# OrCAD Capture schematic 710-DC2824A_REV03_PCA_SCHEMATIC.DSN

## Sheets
1 PAGE3: size A
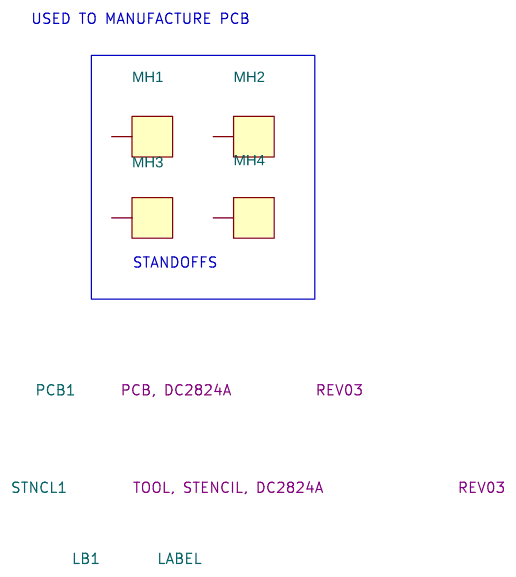
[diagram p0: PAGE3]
2 PAGE2: size Custom; company: ANALOG DEVICES; note: DEMO BOARD BILL OF MATERIALS; note: 25A MONOLITHIC SYNCHRONOUS STEP-DOWN
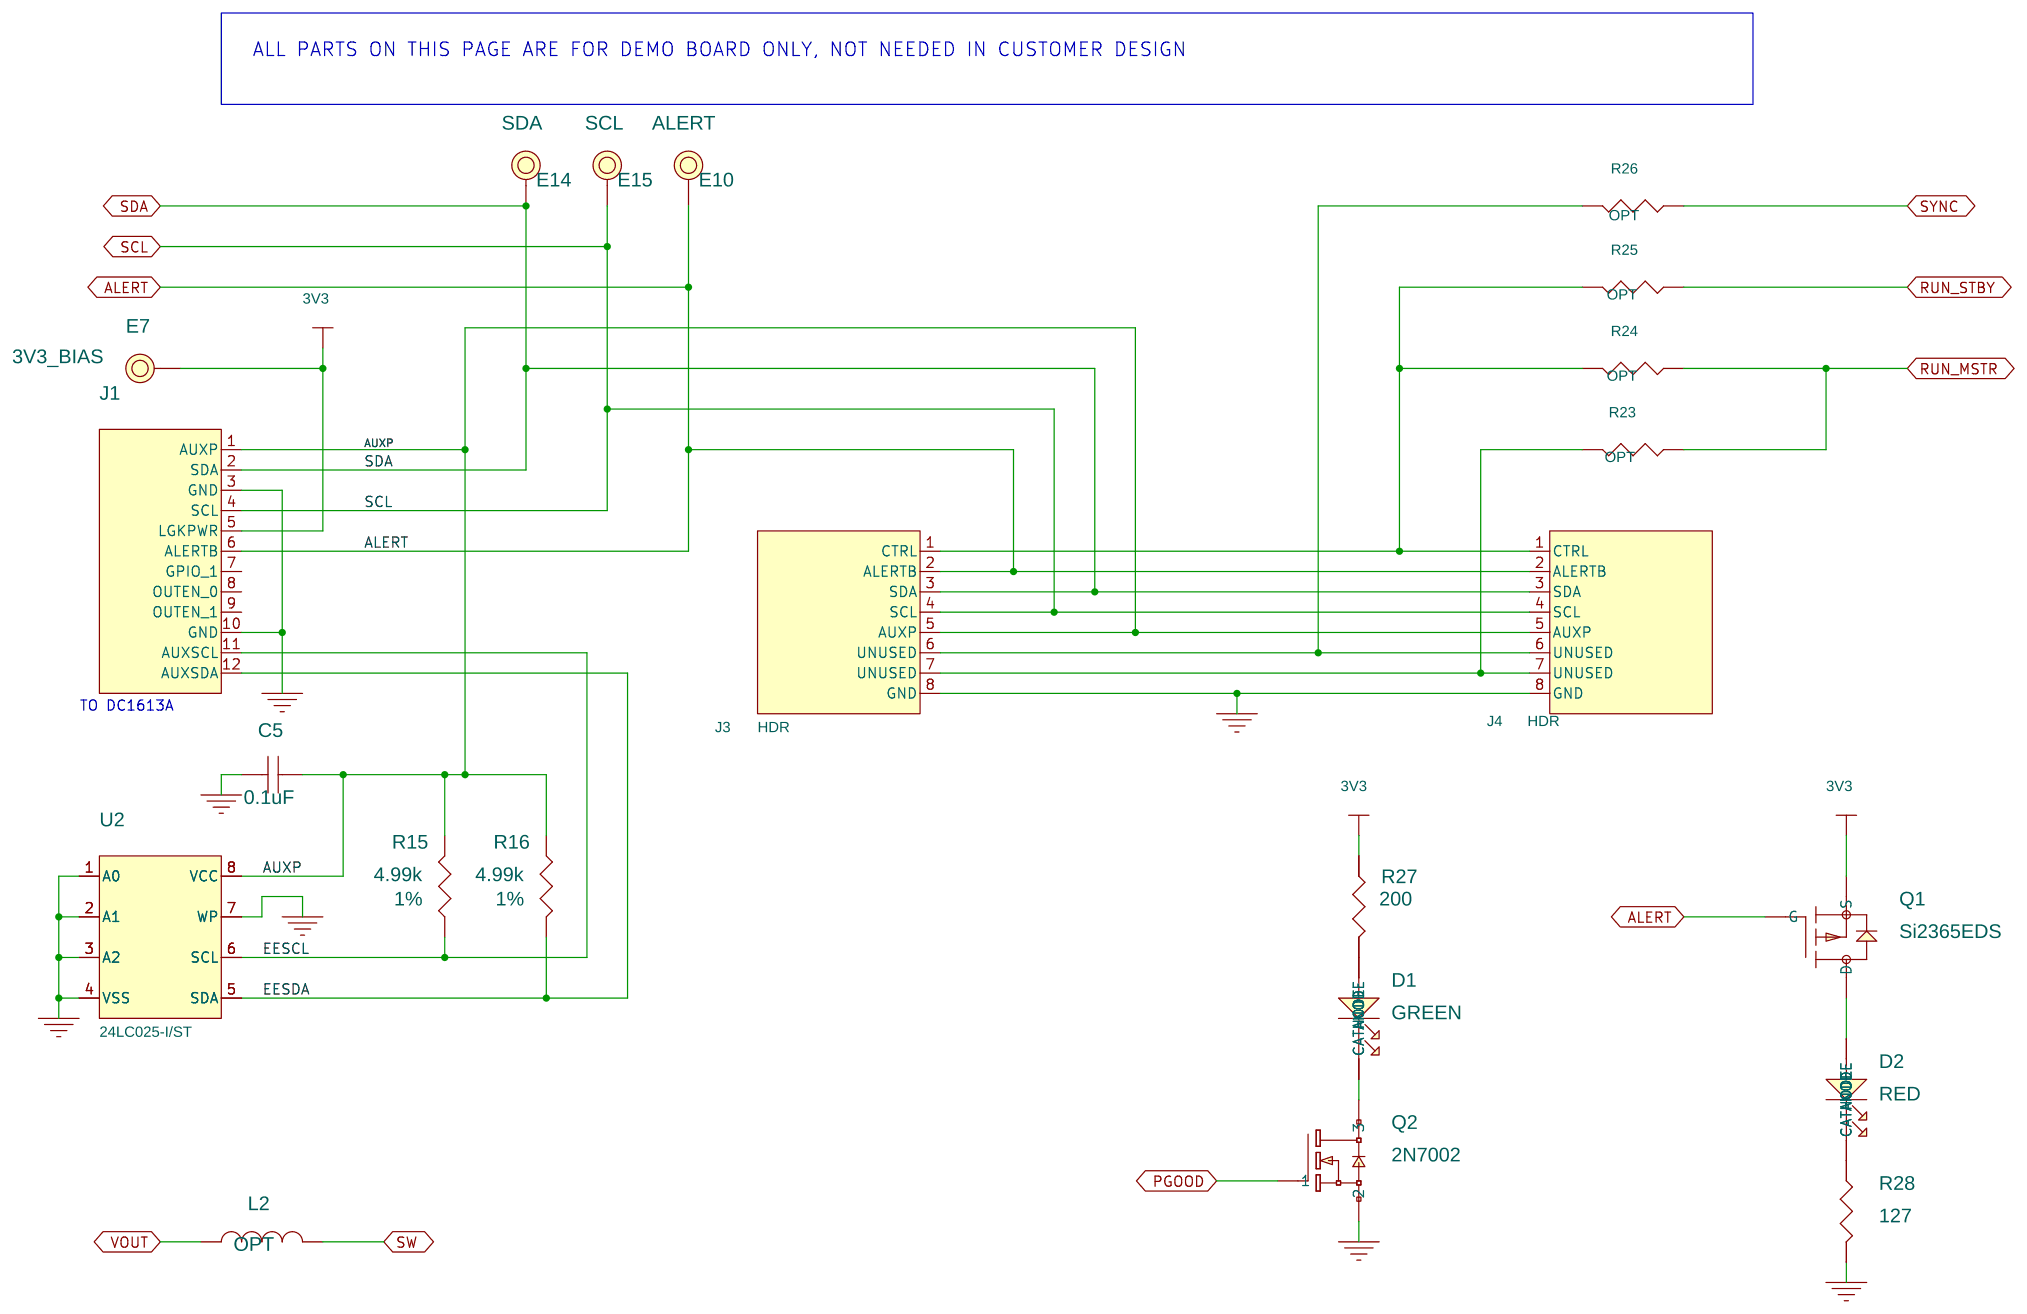
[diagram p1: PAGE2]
3 PAGE1: size Custom; company: ANALOG DEVICES; note: DEMO BOARD BILL OF MATERIALS; note: 25A MONOLITHIC SYNCHRONOUS STEP-DOWN
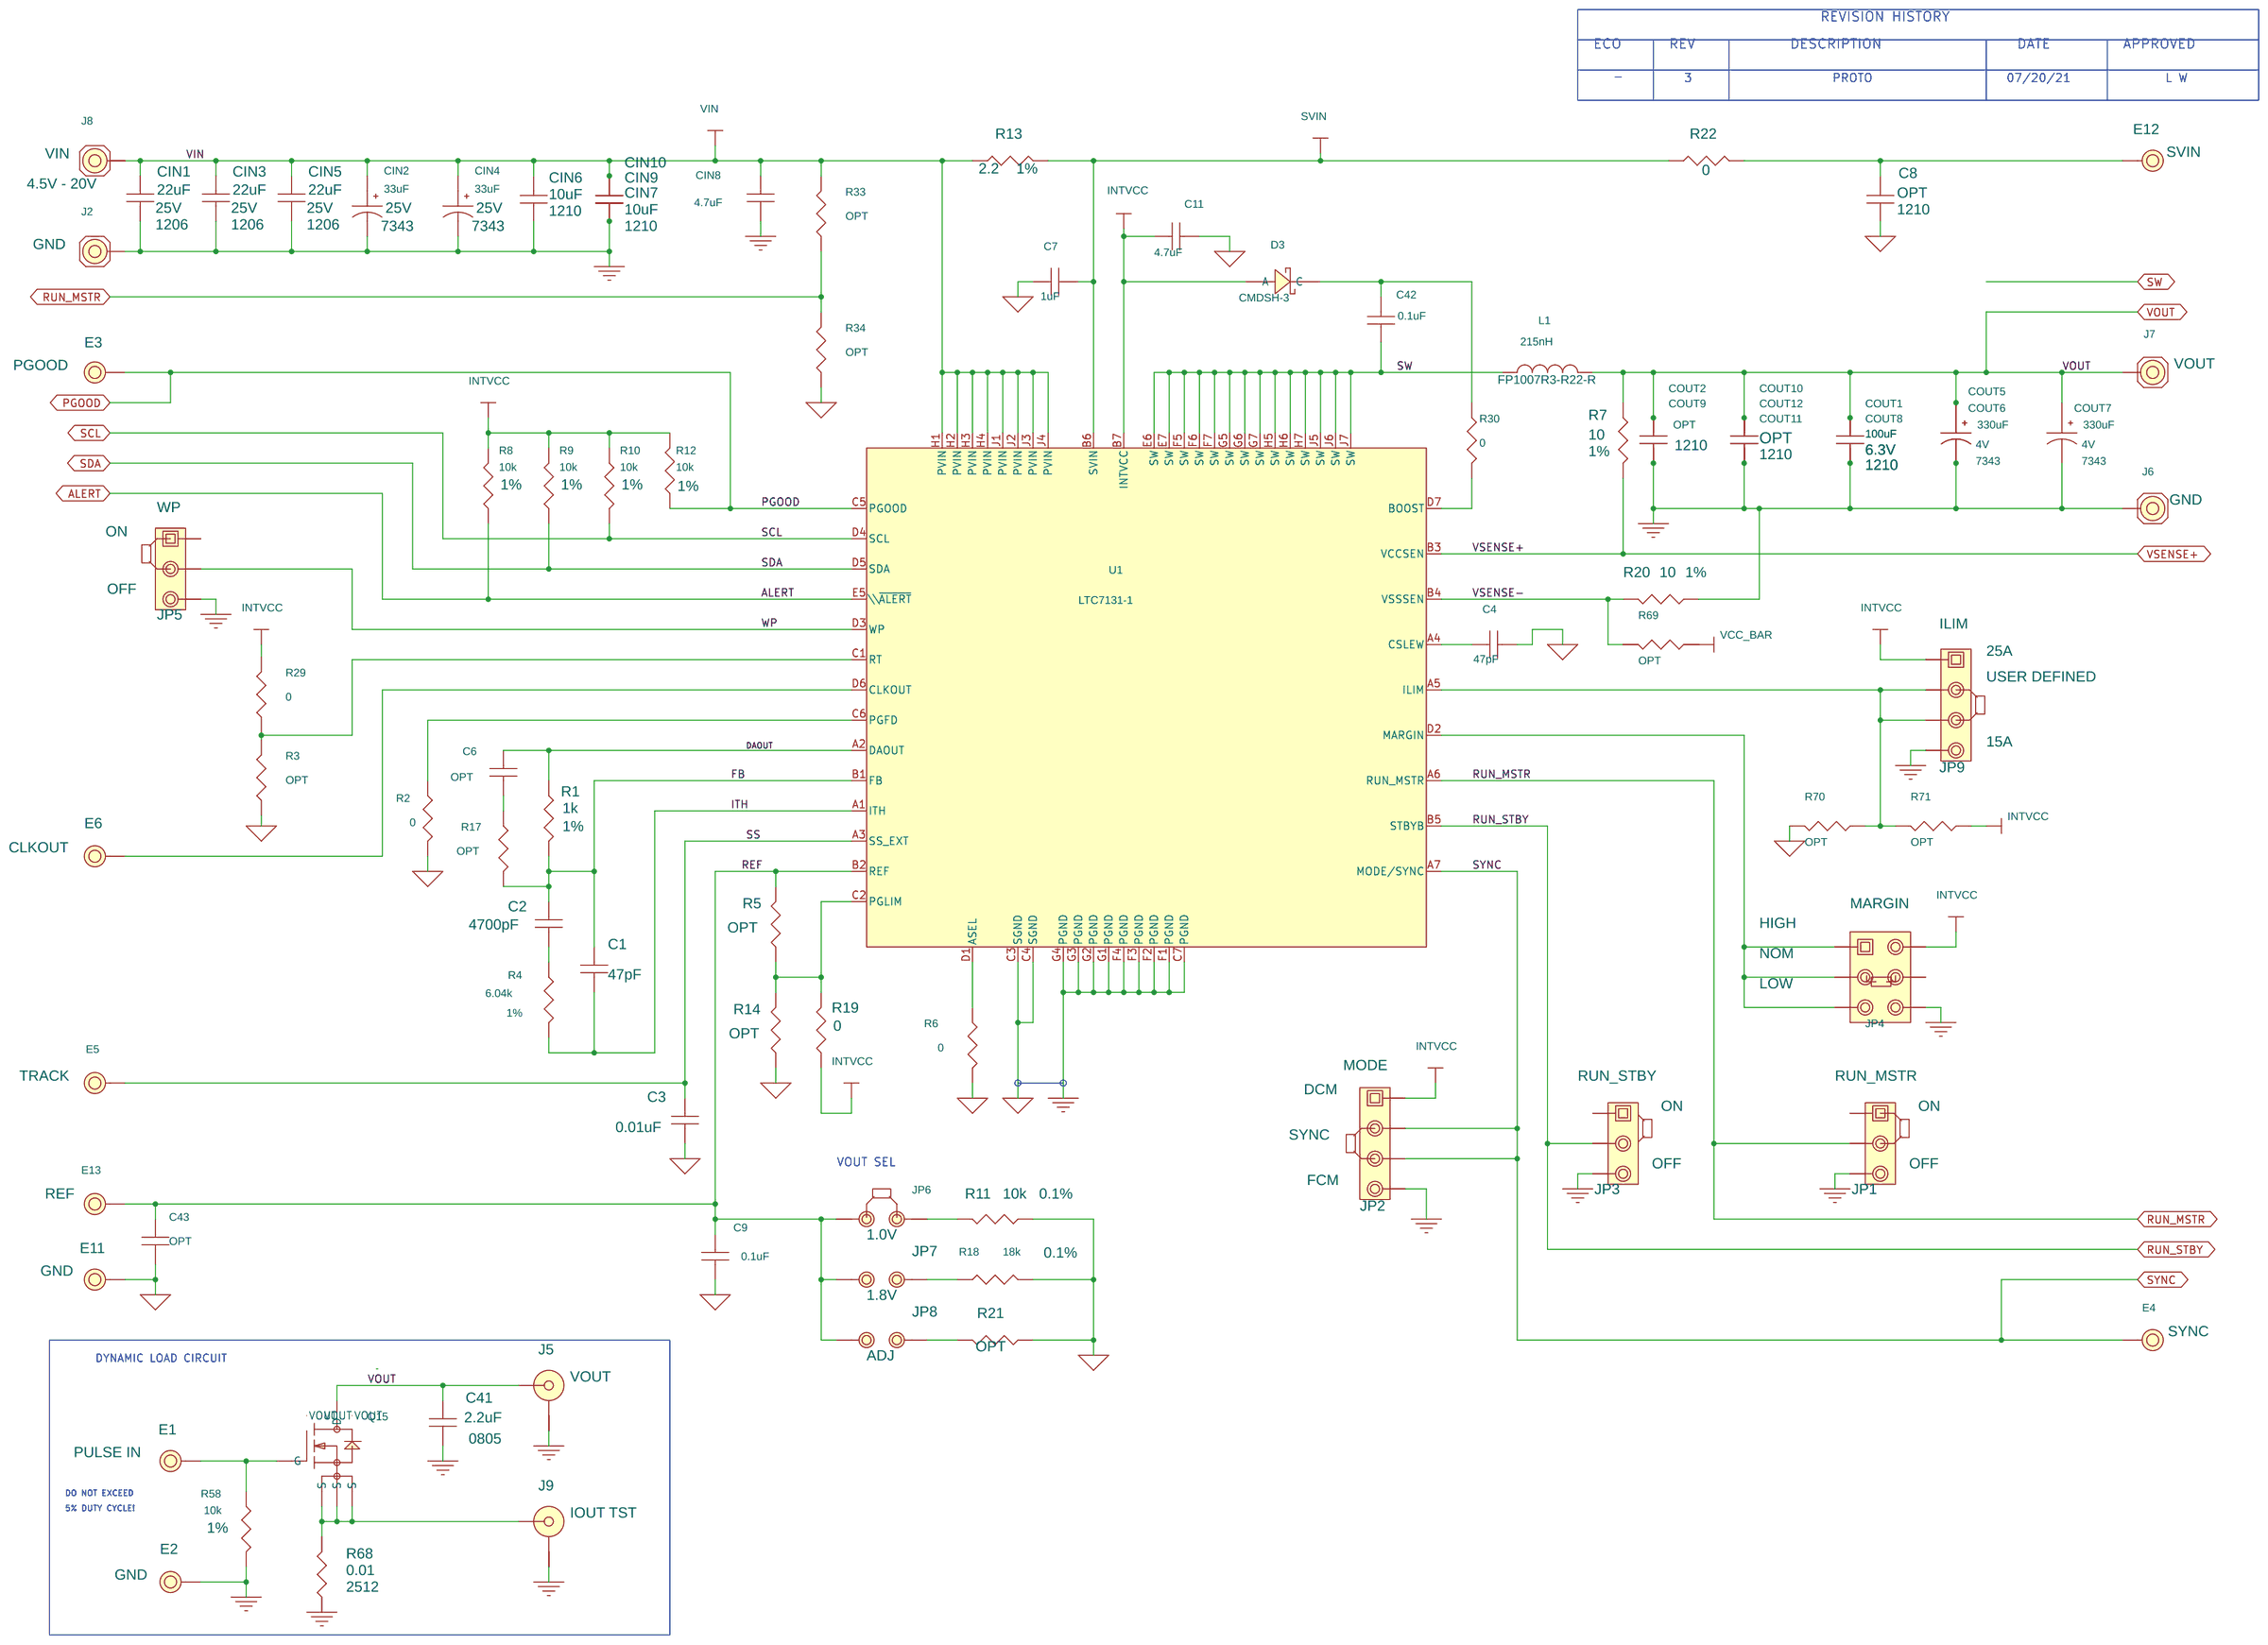
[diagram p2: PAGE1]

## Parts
sheet PAGE1
C1  47pF  [CC0603N]
C2  4700pF  [CC0603N]
C3  0.01uF  [CC0603N]
C4  47pF  [CC0603N]
C6  OPT  [CC0603N]
C7  1uF  [CC0603N]
C8  OPT  [CC1210N]
C9  0.1uF  [CC0603N]
C11  4.7uF  [CC0603N]
C41  2.2uF  [CC0805N]
C42  0.1uF  [CC0603N]
C43  OPT  [CC0603N]
CIN1  22uF  [CC1206N]
CIN2  33uF  [CAPMP7343N]
CIN3  22uF  [CC1206N]
CIN4  33uF  [CAPMP7343N]
CIN5  22uF  [CC1206N]
CIN6  10uF  [CC1210N]
CIN7  10uF  [CC1210N]
CIN8  4.7uF  [CC0603N]
CIN9  10uF  [CC1210N]
CIN10  10uF  [CC1210N]
COUT1  100uF  [CC1210N]
COUT2  OPT  [CC1210N]
COUT5  330uF  [CAPMP7343N]
COUT6  330uF  [CAPMP7343N]
COUT7  330uF  [CAPMP7343N]
COUT8  100uF  [CC1210N]
COUT9  OPT  [CC1210N]
COUT10  OPT  [CC1210N]
COUT11  OPT  [CC1210N]
COUT12  OPT  [CC1210N]
D3  CMDSH-3  [SOD-323M]
E1  TEST POINT  [MILLMAX2501]
E2  TEST POINT  [MILLMAX2501]
E3  TEST POINT  [MILLMAX2501]
E4  TEST POINT  [MILLMAX2501]
E5  TEST POINT  [MILLMAX2501]
E6  TEST POINT  [MILLMAX2501]
E11  TEST POINT  [MILLMAX2501]
E12  TEST POINT  [MILLMAX2501]
E13  TEST POINT  [MILLMAX2501]
J2  STUD,#10-32  [PENN-KFH-032]
J5  RF,BNC  [CONNEX-112404]
J6  STUD,#10-32  [PENN-KFH-032]
J7  STUD,#10-32  [PENN-KFH-032]
J8  STUD,#10-32  [PENN-KFH-032]
J9  RF,BNC  [CONNEX-112404]
JP1  HDR  [HD1X3-079]
JP2  HDR  [HD1X4-079]
JP3  HDR  [HD1X3-079]
JP4  HDR.  [HD2X3-079]
JP5  HDR  [HD1X3-079]
JP6  HDR  [SIP\2P\2MM]
JP7  HDR  [SIP\2P\2MM]
JP8  HDR  [SIP\2P\2MM]
JP9  HDR  [HD1X4-079]
L1  215nH  [EATON-FP1007]
Q15  RJK0305DPB-02  [RENESAS-LFPAK]
R1  1k  [CR0603N]
R2  0  [CR0603N]
R3  OPT  [CR0603N]
R4  6.04k  [CR0603N]
R5  OPT  [CR0603N]
R6  0  [CR0603N]
R7  10  [CR0603N]
R8  10k  [CR0603N]
R9  10k  [CR0603N]
R10  10k  [CR0603N]
R11  10k  [CR0603N]
R12  10k  [CR0603N]
R13  2.2  [CR0603N]
R14  OPT  [CR0603N]
R17  OPT  [CR0603N]
R18  18k  [CR0603N]
R19  0  [CR0603N]
R20  10  [CR0603N]
R21  OPT  [CR0603N]
R22  0  [CR0603N]
R29  0  [CR0603N]
R30  0  [CR0603N]
R33  OPT  [CR0603N]
R34  OPT  [CR0603N]
R58  10k  [CR0603N]
R68  0.01  [CR2512N]
R69  OPT  [CR0603N]
R70  OPT  [CR0603N]
R71  OPT  [CR0603N]
U1  LTC7131-1  [LTC-BGA-63-1988]
XJP1  SHUNT
XJP2  SHUNT
XJP3  SHUNT
XJP4  SHUNT
XJP5  SHUNT
XJP6  SHUNT
XJP9  SHUNT
sheet PAGE2
C5  0.1uF  [CC0603N]
D1  GREEN  [LED_0603]
D2  RED  [LED_0603]
E7  TEST POINT  [MILLMAX2501]
E10  TEST POINT  [MILLMAX2501]
E14  TEST POINT  [MILLMAX2501]
E15  TEST POINT  [MILLMAX2501]
J1  SHROUDED HDR  [HD2X6-079-MOLEX]
J3  HDR  [NPPN042FJFN]
J4  HDR  [NPPN042FJFN-RC]
L2  OPT  [IND\CLCRFT\XEL6030]
Q1  Si2365EDS  [SOT23-3N]
Q2  2N7002  [SOT23-3N]
R15  4.99k  [CR0603N]
R16  4.99k  [CR0603N]
R23  OPT  [CR0603N]
R24  OPT  [CR0603N]
R25  OPT  [CR0603N]
R26  OPT  [CR0603N]
R27  200  [CR0603N]
R28  127  [CR0603N]
U2  24LC025-I/ST  [MICROCHIP-TSSOP-8]
sheet PAGE3
LB1  LABEL  [895-0154_REV01]
MH1  STANDOFF  [KEYSTONE_8829-8834]
MH2  STANDOFF  [KEYSTONE_8829-8834]
MH3  STANDOFF  [KEYSTONE_8829-8834]
MH4  STANDOFF  [KEYSTONE_8829-8834]
PCB1  PCB, DC2824A
STNCL1  TOOL, STENCIL, DC2824A

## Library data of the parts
C1 = CAP: CAP.,47pF,C0G,50V,5%,0603; ALT_SYMBOLS: null; CLASS: DISCRETE; Dielectric Type: C0G; Inventory Qty: 35000; Manufacturer: MURATA; Manufacturer PN: GRM1885C1H470JA01D; PART_NUMBER: 150-0054; Package Size: 0603; Rated Voltage: 50V; Tolerance: 5%; UserField01: null
C2 = CAP: CAP.,4700pF,X7R,50V,10%,0603; CLASS: DISCRETE; Dielectric Type: X7R; FPLIST: CC0603N,CC0603L,CC0603M; Inventory Qty: 34424; Manufacturer: AVX; Manufacturer PN: 06035C472KAT2A; PART_NUMBER: 150-2034; Package Size: 0603; Part Number: AVX 06035C472KAT2A; Rated Voltage: 50V; Tolerance: 10%
C3 = CAP: CAP.,0.01uF,X7R,25V,10%,0603; ALT_SYMBOLS: null; CLASS: DISCRETE; Dielectric Type: X7R; Inventory Qty: 53862; Manufacturer: AVX; Manufacturer PN: 06033C103KAT2A; PART_NUMBER: 150-3341; Package Size: 0603; Package Type: SMD; Part Number: AVX 06033C103KAT2A; Rated Voltage: 25V; Tolerance: 10%; UserField01: null
C4 = CAP: CAP.,47pF,X7R,50V,10%,0603; CLASS: DISCRETE; Dielectric Type: X7R; FPLIST: CC0603N,CC0603L,CC0603M; Inventory Qty: 400; Manufacturer: AVX; Manufacturer PN: 06035C470KAT2A; PART_NUMBER: 150-2319; Package Size: 0603; Rated Voltage: 50V; Tolerance: 10%
C6 = CAP: CAP., OPTION, 0603; CLASS: DISCRETE; FPLIST: CC0603N,CC0603L,CC0603M; PART_NUMBER: 150-3038; Package Size: 0603; Package Type: SMD; Part Number: OPTION
C7 = CAP: CAP.,1uF,X7R,25V,10%,0603; CLASS: DISCRETE; Dielectric Type: X7R; FPLIST: CC0603N,CC0603L,CC0603M; Inventory Qty: 15514; Manufacturer: KEMET; Manufacturer PN: C0603C105K3RACTU; PART_NUMBER: 150-0447; Package Size: 0603; Part Number: MURATA GRJ188R71E105KE11D; Rated Voltage: 25V; Tolerance: 10%
C8 = CAP: CAP., OPTION, 1210; CLASS: DISCRETE; FPLIST: CC1210N,CC1210L,CC1210M; PART_NUMBER: 150-3035; Package Size: 1210; Package Type: SMD; Part Number: OPTION
C9 = CAP: CAP.,0.1uF,X7R,50V,10%,0603; CLASS: DISCRETE; Dielectric Type: X7R; Inventory Qty: 33131; Manufacturer: AVX; Manufacturer PN: 06035C104KAT2A; PART_NUMBER: 150-0102; Package Size: 0603; Rated Voltage: 50V; Tolerance: 10%
C11 CIN8 = CAP: CAP.,4.7uF,X5R,25V,20%,0603; CLASS: DISCRETE; Dielectric Type: X5R; FPLIST: CC0603N,CC0603L,CC0603M; Inventory Qty: 13182; Manufacturer: MURATA; Manufacturer PN: GRM188R61E475ME11D; PART_NUMBER: 150-2378; Package Size: 0603; Part Number: TDK C1608X5R1E475M080AC; Rated Voltage: 25V; Tolerance: 20%
C41 = CAP: CAP.,2.2uF,X7R,25V,10%,0805; CLASS: DISCRETE; Dielectric Type: X7R; FPLIST: CC0805N,CC0805L,CC0805M; Inventory Qty: 6022; Manufacturer: MURATA; Manufacturer PN: GRM21BR71E225KA73L; PART_NUMBER: 150-0207; Package Size: 0805; Part Number: MURATA GRM21BR71E225KA73L; Rated Voltage: 25V; Tolerance: 10%
C42 = CAP: CAP.,0.1uF,X7R,25V,10%,0603; CLASS: DISCRETE; Dielectric Type: X7R; FPLIST: CC0603N,CC0603L,CC0603M; Inventory Qty: 50244; Manufacturer: AVX; Manufacturer PN: 06033C104KAT2A; PART_NUMBER: 150-0065; Package Size: 0603; Part Number: MURATA GRJ188R71E105KE11D; Rated Voltage: 25V; Tolerance: 10%
C43 = CAP: CAP., OPTION, 0603; CLASS: DISCRETE; PART_NUMBER: 150-3038; Package Size: 0603; Package Type: SMD
CIN1 CIN3 = CAP: CAP.,22uF,X5R,25V,10%,1206; CLASS: DISCRETE; Dielectric Type: X5R; FPLIST: CC1206N,CC1206L,CC1206M; Inventory Qty: 8019; Manufacturer: AVX; Manufacturer PN: 12063D226KAT2A; PART_NUMBER: 150-0253; Package Size: 1206; Part Number: MURATA GRM31CR61E226KE15L; Rated Voltage: 25V; Tolerance: 10%
CIN2 CIN4 = CAP_P: CAP.,33uF,ALUM POLY,25V,20%,7343; CLASS: DISCRETE; Dielectric Type: ALUM POLY; FPLIST: CAPMP7343N,CAPMP7343L,CAPMP7343M; Inventory Qty: 1684; Manufacturer: PANASONIC; Manufacturer PN: EEFCX1E330R; PART_NUMBER: 150-0448; Package Size: 7343; Part Number: PANASONIC EEFCX1E330R; Rated Voltage: 25V; Tolerance: 20%
CIN5 = CAP: CAP.,22uF,X5R,25V,10%,1206; CLASS: DISCRETE; Dielectric Type: X5R; FPLIST: CC1206N,CC1206L,CC1206M; Manufacturer: MURATA; Manufacturer PN: GRM31CR61E226KE15L; PART_NUMBER: 150-0253; Package Size: 1206; Part Number: MURATA GRM31CR61E226KE15L; Rated Voltage: 25V; Tolerance: 10%
CIN6 CIN7 CIN9 CIN10 = CAP: CAP.,10uF,X7R,25V,10%,1210; CLASS: DISCRETE; Dielectric Type: X7R; FPLIST: CC1210N,CC1210L,CC1210M; Manufacturer: MURATA; Manufacturer PN: GRM32DR71E106KA12L; PART_NUMBER: 150-0282; Package Size: 1210; Part Number: MURATA GRM32DR71E106KA12L; Rated Voltage: 25V; Tolerance: 10%
COUT1 COUT8 = CAP: CAP.,100uF,X5R,6.3V,20%,1210,NO SUBS ALLOWED; CLASS: DISCRETE; Dielectric Type: X5R; Inventory Qty: 0; Manufacturer: MURATA; Manufacturer PN: GRM32ER60J107ME20L; PART_NUMBER: 150-1002; Package Size: 1210; Rated Voltage: 6.3V; Tolerance: 20%
COUT2 COUT9-COUT12 = CAP: CAP., OPTION, 1210; CLASS: DISCRETE; FPLIST: CC1210N,CC1210L,CC1210M; PART_NUMBER: 150-3035; Package Size: 1210; Package Type: SMD; Part Number: MURATA GRM32ER60J107ME20L
COUT5-COUT7 = CAP_P: CAP.,330uF,ALUM POLY,4V,20%,7343; ALT_SYMBOLS: null; CLASS: DISCRETE; Dielectric Type: ALUM POLY; FPLIST: CAPMP7343N,CAPMP7343L,CAPMP7343M; Inventory Qty: 2440; Manufacturer: PANASONIC; Manufacturer PN: EEF-SX0G331XE; PART_NUMBER: 150-0823; Package Size: 7343; Part Number: PANASONIC 6TPF330M9L; Rated Voltage: 4V; Tolerance: 20%; UserField01: null
D3 = DIODE_SCHOTTKY_A: DIODE,SCHOTTKY,30V,100mA,SOD-323; CLASS: DISCRETE; FPLIST: SOD323,SOD-323N,SOD-323M; Manufacturer: CENTRAL SEMI.; Manufacturer PN: CMHSH-3 TR; PART_NUMBER: 210-0331; Package Size: SOD-323; Package Type: SOD-323; Part Number: CENTRAL SEMI. CMHSH-3 TR
E1 = TESTPOINT_.219_MILL-MAX_2501: TEST POINT,TURRET,0.094" MTG. HOLE,PCB 0.062" THK; CLASS: IO; FPLIST: MILLMAX2501,MILLMAX2501_ALT1; Inventory Qty: 471322; Label: PULSE IN; Manufacturer: MILL-MAX; Manufacturer PN: 2501-2-00-80-00-00-07-0; PART_NUMBER: 260-0003; Part Number: MILL MAX 2501-2-00-80-00-00-07-0
E2 E11 = TESTPOINT_.219_MILL-MAX_2501: TEST POINT,TURRET,0.094" MTG. HOLE,PCB 0.062" THK; CLASS: IO; FPLIST: MILLMAX2501,MILLMAX2501_ALT1; Inventory Qty: 471322; Label: GND; Manufacturer: MILL-MAX; Manufacturer PN: 2501-2-00-80-00-00-07-0; PART_NUMBER: 260-0003; Part Number: MILL MAX 2501-2-00-80-00-00-07-0
E3 = TESTPOINT_.219_MILL-MAX_2501: TEST POINT,TURRET,0.094" MTG. HOLE,PCB 0.062" THK; CLASS: IO; FPLIST: MILLMAX2501,MILLMAX2501_ALT1; Inventory Qty: 471322; Label: PGOOD; Manufacturer: MILL-MAX; Manufacturer PN: 2501-2-00-80-00-00-07-0; PART_NUMBER: 260-0003; Part Number: MILL MAX 2501-2-00-80-00-00-07-0
E4 = TESTPOINT_.219_MILL-MAX_2501: TEST POINT,TURRET,0.094" MTG. HOLE,PCB 0.062" THK; CLASS: IO; FPLIST: MILLMAX2501,MILLMAX2501_ALT1; Inventory Qty: 471322; Label: SYNC; Manufacturer: MILL-MAX; Manufacturer PN: 2501-2-00-80-00-00-07-0; PART_NUMBER: 260-0003; Part Number: MILL MAX 2501-2-00-80-00-00-07-0
E5 = TESTPOINT_.219_MILL-MAX_2501: TEST POINT,TURRET,0.094" MTG. HOLE,PCB 0.062" THK; CLASS: IO; FPLIST: MILLMAX2501,MILLMAX2501_ALT1; Inventory Qty: 471322; Label: TRACK; Manufacturer: MILL-MAX; Manufacturer PN: 2501-2-00-80-00-00-07-0; PART_NUMBER: 260-0003; Part Number: MILL MAX 2501-2-00-80-00-00-07-0
E6 = TESTPOINT_.219_MILL-MAX_2501: TEST POINT,TURRET,0.094" MTG. HOLE,PCB 0.062" THK; CLASS: IO; FPLIST: MILLMAX2501,MILLMAX2501_ALT1; Inventory Qty: 471322; Label: CLKOUT; Manufacturer: MILL-MAX; Manufacturer PN: 2501-2-00-80-00-00-07-0; PART_NUMBER: 260-0003; Part Number: MILL MAX 2501-2-00-80-00-00-07-0
E12 = TESTPOINT_.219_MILL-MAX_2501: TEST POINT,TURRET,0.094" MTG. HOLE,PCB 0.062" THK; CLASS: IO; FPLIST: MILLMAX2501,MILLMAX2501_ALT1; Inventory Qty: 471322; Label: SVIN; Manufacturer: MILL-MAX; Manufacturer PN: 2501-2-00-80-00-00-07-0; PART_NUMBER: 260-0003; Part Number: MILL MAX 2501-2-00-80-00-00-07-0
E13 = TESTPOINT_.219_MILL-MAX_2501: TEST POINT,TURRET,0.094" MTG. HOLE,PCB 0.062" THK; CLASS: IO; FPLIST: MILLMAX2501,MILLMAX2501_ALT1; Inventory Qty: 471322; Label: REF; Manufacturer: MILL-MAX; Manufacturer PN: 2501-2-00-80-00-00-07-0; PART_NUMBER: 260-0003; Part Number: MILL MAX 2501-2-00-80-00-00-07-0
J2 J6 = PEM-KFH: EVAL BOARD STUD HARDWARE SET, #10-32; 10th Part Field: 4.5V - 20V; 9th Part Field: GND; CLASS: DISCRETE; Comments: CONSISTS OF QTY(1) STUD, 769-0012; QTY(1) RING LUG, 769-0013;QTY(2) HEX NUT,BRASS,761-0013; QTY(1) WASHER,#10 LOCK, 762-0021; Manufacturer: ANALOG DEVICES; Manufacturer PN: 720-0010; PART_NUMBER: 720-0010
J5 = BNC_50_OHM_112404_B: CONN.,RF,BNC,RCPT JACK,5-PIN,STR,THT,50 OHMS; 1st Part Field: VOUT; CLASS: IO; Inventory Qty: 83605; Manufacturer: AMPHENOL RF; Manufacturer PN: 112404; PART_NUMBER: 250-0427; Part Number: CONNEX 112404
J7 = PEM-KFH: EVAL BOARD STUD HARDWARE SET, #10-32; 10th Part Field: 4.5V - 20V; 9th Part Field: VOUT; CLASS: DISCRETE; Comments: CONSISTS OF QTY(1) STUD, 769-0012; QTY(1) RING LUG, 769-0013;QTY(2) HEX NUT,BRASS,761-0013; QTY(1) WASHER,#10 LOCK, 762-0021; Manufacturer: ANALOG DEVICES; Manufacturer PN: 720-0010; PART_NUMBER: 720-0010
J8 = PEM-KFH: EVAL BOARD STUD HARDWARE SET, #10-32; 10th Part Field: 4.5V - 20V; 9th Part Field: VIN; CLASS: DISCRETE; Comments: CONSISTS OF QTY(1) STUD, 769-0012; QTY(1) RING LUG, 769-0013;QTY(2) HEX NUT,BRASS,761-0013; QTY(1) WASHER,#10 LOCK, 762-0021; Manufacturer: ANALOG DEVICES; Manufacturer PN: 720-0010; PART_NUMBER: 720-0010
J9 = BNC_50_OHM_112404_B: CONN.,RF,BNC,RCPT JACK,5-PIN,STR,THT,50 OHMS; 1st Part Field: IOUT TST; CLASS: IO; Inventory Qty: 83605; Manufacturer: AMPHENOL RF; Manufacturer PN: 112404; PART_NUMBER: 250-0427; Part Number: CONNEX 112404
JP1 = 1X3_A: CONN.,HDR,MALE,1x3,2mm,VERT,STR,THT,NO SUBS. ALLOWED; 11th Part Field: OFF; 12th Part Field: RUN_MSTR; 9th Part Field: ON; CLASS: IO; Inventory Qty: 24962; Manufacturer: Wurth Elektronik; Manufacturer PN: 62000311121; PART_NUMBER: 250-0639; Part Number: WURTH ELEC. 62000311121
JP2 = HDR1X4_ALT1: CONN.,HDR,MALE,1x4,2mm,VERT,STR,THT; 11th Part Field: SYNC; 12th Part Field: FCM; 13tht Part Field: MODE; 9th Part Field: DCM; CLASS: IO; Inventory Qty: 11019; Manufacturer: WURTH ELEKTRONIK; Manufacturer PN: 62000411121; PART_NUMBER: 250-0563; Part Number: WURTH ELEK. 62000411121
JP3 = 1X3_A: CONN.,HDR,MALE,1x3,2mm,VERT,STR,THT,NO SUBS. ALLOWED; 11th Part Field: OFF; 12th Part Field: RUN_STBY; 9th Part Field: ON; CLASS: IO; Inventory Qty: 24962; Manufacturer: Wurth Elektronik; Manufacturer PN: 62000311121; PART_NUMBER: 250-0639; Part Number: WURTH ELEC. 62000311121
JP4 = HDR2X3_ALT1: CONN.,HDR.,MALE,2x3,2mm,VERT,STR,THT; 4th Part Field: HIGH; 5th Part Field: NOM; 7th Part Field: LOW; 9th Part Field: MARGIN; CLASS: IO; Inventory Qty: 15640; Manufacturer: WURTH ELEKTRONIK; Manufacturer PN: 62000621121; PART_NUMBER: 250-0483; Part Number: WURTH ELEK. 62000621121
JP5 = 1X3_A: CONN.,HDR,MALE,1x3,2mm,VERT,STR,THT,NO SUBS. ALLOWED; 11th Part Field: OFF; 12th Part Field: WP; 9th Part Field: ON; CLASS: IO; Inventory Qty: 24962; Manufacturer: Wurth Elektronik; Manufacturer PN: 62000311121; PART_NUMBER: 250-0639; Part Number: WURTH ELEC. 62000311121
JP6 = HDR1X2_ALT1_1: CONN.,HDR,MALE,1x2,2mm,STR, THT; 9th Part Field: 1.0V; CLASS: IO; Inventory Qty: 3718; Manufacturer: WURTH ELEKTRONIK; Manufacturer PN: 62000211121; PART_NUMBER: 250-0507; Part Number: WURTH ELEKTRONIK 62000211121
JP7 = HDR1X2_ALT1: CONN.,HDR,MALE,1x2,2mm,STR, THT; 9th Part Field: 1.8V; CLASS: IO; Inventory Qty: 3718; Manufacturer: WURTH ELEKTRONIK; Manufacturer PN: 62000211121; PART_NUMBER: 250-0507; Part Number: WURTH ELEKTRONIK 62000211121
JP8 = HDR1X2_ALT1_2: CONN.,HDR,MALE,1x2,2mm,STR, THT; 9th Part Field: ADJ; CLASS: IO; Inventory Qty: 3718; Manufacturer: WURTH ELEKTRONIK; Manufacturer PN: 62000211121; PART_NUMBER: 250-0507; Part Number: WURTH ELEKTRONIK 62000211121
JP9 = HDR1X4_ALT1: CONN.,HDR,MALE,1x4,2mm,VERT,STR,THT; 11th Part Field: USER DEFINED; 12th Part Field: 15A; 13tht Part Field: ILIM; 5th Part Field: ON1_CONTROL; 9th Part Field: 25A; CLASS: IO; Inventory Qty: 11019; Manufacturer: WURTH ELEKTRONIK; Manufacturer PN: 62000411121; PART_NUMBER: 250-0563; Part Number: WURTH ELEK. 62000411121
L1 = IND: IND.,215nH,PWR, FERRITE,10%,61A,0.29mOHM,10.4x8.0mm SMD; 5TH PART FIELD: FP1007R3-R22-R; CLASS: DISCRETE; Manufacturer: EATON; Manufacturer PN: FP1007R3-R22-R; PART_NUMBER: 200-0454; Package Size: 10.4x8.0mm SMD; Part Number: EATON FP1007R3-R17-R; Tolerance: +/-10%
Q15 = 5P_N-CH_TYPE1D_0: XSTR.,MOSFET, N-CH,30V,30A,LFPAK; CLASS: DISCRETE; Inventory Qty: 1734; Manufacturer: RENESAS; Manufacturer PN: RJK0305DPB-00#J0; PART_NUMBER: 240-0239; Package Size: SC-100, SOT-669; Package Type: LFPAK; Polarity: MOSFET N-Channel, Metal Oxide; Rated Power: 45W; Rated Voltage: 30V
R1 = RES: RES.,1k OHM,1%,1/10W,0603,AEC-Q200; CLASS: DISCRETE; FPLIST: CR0603N,CR0603L,CR0603M; Inventory Qty: 118691; Manufacturer: VISHAY; Manufacturer PN: CRCW06031K00FKEA; PART_NUMBER: 100-2422; Package Size: 0603; Part Number: VISHAY CRCW06031K00FKEA; Rated Power: 1/10W; Temperature Coefficient: 100ppm; Tolerance: 1%
R2 R6 R19 R22 R29 R30 = RES: RES.,0 OHM,1/10W,0603,AEC-Q200; CLASS: DISCRETE; FPLIST: CR0603N,CR0603L,CR0603M; Inventory Qty: 604702; Manufacturer: VISHAY; Manufacturer PN: CRCW06030000Z0EA; PART_NUMBER: 100-0009; Package Size: 0603; Part Number: VISHAY CRCW06030000Z0EA; Rated Power: 1/10W
R3 R5 R14 R17 R21 R33 R34 R69-R71 = RES: RES., OPTION, 0603; CLASS: DISCRETE; FPLIST: CR0603N,CR0603L,CR0603M; PART_NUMBER: 100-2374; Package Size: 0603; Part Number: OPTION
R4 = RES: RES.,6.04k OHMS,1%,1/10W,0603,AEC-Q200; ALT_SYMBOLS: null; CLASS: DISCRETE; FPLIST: CR0603N,CR0603L,CR0603M; Inventory Qty: 10142; Manufacturer: KOA SPEER; Manufacturer PN: RK73H1JTTD6041F; PART_NUMBER: 100-2368; Package Size: 0603; Part Number: VISHAY CRCW06035K49FKEA; Rated Power: 1/10W; Temperature Coefficient: 100ppm/C; Tolerance: 1%
R7 R20 = RES: RES.,10 OHMS,1%,1/10W,0603; CLASS: DISCRETE; FPLIST: CR0603N,CR0603L,CR0603M; Inventory Qty: 150056; Manufacturer: VISHAY; Manufacturer PN: CRCW060310R0FKEA; PART_NUMBER: 100-2306; Package Size: 0603; Part Number: VISHAY CRCW060310R0FKEA; Rated Power: 1/10W; Temperature Coefficient: 100ppm/C; Tolerance: 1%
R8-R10 R58 = RES: RES.,10k OHMS,1%,1/10W,0603,AEC-Q200; CLASS: DISCRETE; FPLIST: CR0603N,CR0603L,CR0603M; Inventory Qty: 134064; Manufacturer: VISHAY; Manufacturer PN: CRCW060310K0FKEA; PART_NUMBER: 100-2012; Package Size: 0603; Part Number: VISHAY CRCW060310K0FKEA; Rated Power: 1/10W; Temperature Coefficient: +/-100ppm/C; Tolerance: 1%
R11 = RES: RES.,10k OHMS,0.1%,1/8W,0603,ANTI-SULFUR, AEC-Q200; CLASS: DISCRETE; FPLIST: CR0603N,CR0603L,CR0603M; Inventory Qty: 15192; Manufacturer: VISHAY; Manufacturer PN: TNPW060310K0BEEA; PART_NUMBER: 100-2059; Package Size: 0603; Part Number: VISHAY TNPW060310K0BEEA; Rated Power: 1/8W; Temperature Coefficient: +/-25ppm; Tolerance: 0.1%
R12 = RES: RES.,10k OHMS,1%,1/10W,0603,AEC-Q200; CLASS: DISCRETE; FPLIST: CR0603N,CR0603L,CR0603M; Inventory Qty: 134064; Manufacturer: VISHAY; Manufacturer PN: CRCW060310K0FKEA; PART_NUMBER: 100-2012; Package Size: 0603; Rated Power: 1/10W; Temperature Coefficient: +/-100ppm/C; Tolerance: 1%
R13 = RES: RES.,AEC-Q200,2.2 OHMS,1%,1/10W,0603; ALT_SYMBOLS: null; CLASS: DISCRETE; Manufacturer: VISHAY; Manufacturer PN: CRCW06032R20FKEA; PART_NUMBER: 100-2956; Package Size: 0603; Part Number: VISHAY CRCW06032R20FKEA; Rated Power: 1/10W; Temperature Coefficient: 100ppm; Tolerance: 1%
R18 = RES: RES.,18k OHMS,0.1%,1/10W,0603,AEC-Q200; CLASS: DISCRETE; FPLIST: CR0603N,CR0603L,CR0603M; Inventory Qty: 4992; Manufacturer: VISHAY; Manufacturer PN: TNPW060318K0BEEA; PART_NUMBER: 100-2007; Package Size: 0603; Part Number: VISHAY TNPW060318K0BEEA; Rated Power: 1/10W; Temperature Coefficient: +/-25ppm/K; Tolerance: 0.1%
R68 = RES: RES.,0.01 OHM,1%,1W,2512,METAL,SENSE; CLASS: DISCRETE; FPLIST: CR2512N,CR2512L,CR2512M; Inventory Qty: 13175; Manufacturer: PANASONIC; Manufacturer PN: ERJM1WSF10MU; PART_NUMBER: 100-0248; Package Size: 2512; Part Number: PANASONIC ERJM1WSF10MU; Rated Power: 1W; Temperature Coefficient: 100ppm/C; Tolerance: 1%
U1 = LTC7131-BGA: IC,25A Monolithic Synchronous DC/DC Step-Down Converter with PMBUS Interface,BGA; CLASS: IC; Inventory Qty: 0; Manufacturer: ANALOG DEVICES; Manufacturer PN: LTC7131IY-1#PBF; PART_NUMBER: LTC7131IY-1#PBF; Package Size: 7.50X6.25X2.22; Package Type: BGA; Part Number: LINEAR TECH. LTC7131IY#PBF; Supply Voltage: 4.5V - 20V
XJP1-XJP3 XJP5 XJP6 XJP9 = SHUNT_2MM: CONN.,SHUNT,FEMALE,2 POS,2mm; CLASS: IO; Inventory Qty: 66882; Manufacturer: Wurth Elektronik; Manufacturer PN: 60800213421; PART_NUMBER: 250-0485; Part Number: WURTH ELEK. 60800213421
XJP4 = SHUNT_2MM_C: CONN.,SHUNT,FEMALE,2 POS,2mm; CLASS: IO; Inventory Qty: 66882; Manufacturer: Wurth Elektronik; Manufacturer PN: 60800213421; PART_NUMBER: 250-0485
C5 = CAP: CAP.,0.1uF,X7R,50V,10%,0603; CLASS: DISCRETE; Dielectric Type: X7R; FPLIST: CC0603N,CC0603L,CC0603M; Manufacturer: MURATA; Manufacturer PN: GRM188R71H104KA93D; PART_NUMBER: 150-0102; Package Size: 0603; Part Number: MURATA GRM188R71H104KA93D; Rated Voltage: 50V; Tolerance: 10%
D1 = LED: LED,GREEN,WATER CLEAR,0603; CLASS: DISCRETE; Inventory Qty: 6913; Manufacturer: WURTH ELEKTRONIK; Manufacturer PN: 150060GS75000; PART_NUMBER: 270-0057; Package Type: 0603; Part Number: WURTH ELEK. 150060GS75000
D2 = LED: LED,RED,WATER CLEAR,0603; CLASS: DISCRETE; Inventory Qty: 928; Manufacturer: WURTH ELEKTRONIK; Manufacturer PN: 150060RS75000; PART_NUMBER: 270-0071; Package Type: 0603; Part Number: WURTH ELEK. 150060RS75000
E7 = TESTPOINT_.219_MILL-MAX_2501: TEST POINT,TURRET,0.094" MTG. HOLE,PCB 0.062" THK; CLASS: IO; FPLIST: MILLMAX2501,MILLMAX2501_ALT1; Inventory Qty: 471322; Label: 3V3_BIAS; Manufacturer: MILL-MAX; Manufacturer PN: 2501-2-00-80-00-00-07-0; PART_NUMBER: 260-0003; Part Number: MILL MAX 2501-2-00-80-00-00-07-0
E10 = TESTPOINT_.219_MILL-MAX_2501: TEST POINT,TURRET,0.094" MTG. HOLE,PCB 0.062" THK; CLASS: IO; FPLIST: MILLMAX2501,MILLMAX2501_ALT1; Inventory Qty: 471322; Label: ALERT; Manufacturer: MILL-MAX; Manufacturer PN: 2501-2-00-80-00-00-07-0; PART_NUMBER: 260-0003; Part Number: MILL MAX 2501-2-00-80-00-00-07-0
E14 = TESTPOINT_.219_MILL-MAX_2501: TEST POINT,TURRET,0.094" MTG. HOLE,PCB 0.062" THK; CLASS: IO; FPLIST: MILLMAX2501,MILLMAX2501_ALT1; Inventory Qty: 471322; Label: SDA; Manufacturer: MILL-MAX; Manufacturer PN: 2501-2-00-80-00-00-07-0; PART_NUMBER: 260-0003; Part Number: MILL MAX 2501-2-00-80-00-00-07-0
E15 = TESTPOINT_.219_MILL-MAX_2501: TEST POINT,TURRET,0.094" MTG. HOLE,PCB 0.062" THK; CLASS: IO; FPLIST: MILLMAX2501,MILLMAX2501_ALT1; Inventory Qty: 471322; Label: SCL; Manufacturer: MILL-MAX; Manufacturer PN: 2501-2-00-80-00-00-07-0; PART_NUMBER: 260-0003; Part Number: MILL MAX 2501-2-00-80-00-00-07-0
J1 = CONN._FCI_12_POS_2MM: CONN.,SHROUDED HDR,MALE,2x6,2mm,VERT, STR, THT; CLASS: IO; FPLIST: HD2X6-079-MOLEX,AMPHENOL-FCI-9814-X06-12; Manufacturer: FCI; Manufacturer PN: 98414-G06-12ULF; PART_NUMBER: 250-0433; Part Number: FCI 98414-G06-12ULF
J3 = PMBUS_HEADER: CONN.,HDR,MALE,2x4,2mm,R/A THT; CLASS: IO; Inventory Qty: 4992; Manufacturer: MOLEX; Manufacturer PN: 87760-0816; PART_NUMBER: 250-0751; Part Number: MOLEX 87760-0816
J4 = PMBUS_HEADER: CONN.,HDR,FEMALE,2x4,2mm,R/A THT; CLASS: IO; Inventory Qty: 1242; Manufacturer: SULLINS CONNECTOR SOLUTIONS; PART_NUMBER: 250-0750; Part Number: SULLINS NPPN042FJFN-RC
L2 = IND: IND., OPTION; CLASS: DISCRETE; PART_NUMBER: 200-0129; Package Size: USER ASSIGNED
Q1 = 3P_P-CH_TYPE1A: XSTR.,MOSFET, P-CH,20V,5.9A,TO-236 (SOT23-3); CLASS: DISCRETE; Inventory Qty: 16867; Manufacturer: VISHAY; Manufacturer PN: Si2365EDS-T1-GE3; PART_NUMBER: 240-0119; Package Size: SOT-23; Package Type: TO-236 (SOT23-3); Part Number: VISHAY Si2365EDS-T1-GE3; Rated Voltage: 20V
Q2 = 2N7002_SOT-23: XSTR.,MOSFET N-CH,60V,300mA,SOT-23; CLASS: DISCRETE; Inventory Qty: 7069; Manufacturer: VISHAY; Manufacturer PN: 2N7002K-T1-GE3; PART_NUMBER: 240-0125; Package Size: SOT-23; Package Type: SOT-23; Part Number: VISHAY 2N7002K-T1-GE3; Rated Voltage: 60V
R15 R16 = RES: RES.,4.99k OHMS,1%,1/10W,0603; CLASS: DISCRETE; FPLIST: CR0603N,CR0603L,CR0603M; Manufacturer: VISHAY; Manufacturer PN: CRCW06034K99FKEA; PART_NUMBER: 100-2510; Package Size: 0603; Part Number: VISHAY CRCW06034K99FKEA; Rated Power: 1/10W; Temperature Coefficient: 100ppm; Tolerance: 1%
R23-R26 = RES: RES., OPTION, 0603; CLASS: DISCRETE; FPLIST: CR0603N,CR0603L,CR0603M; PART_NUMBER: 100-2374; Package Size: 0603
R27 = RES: RES.,200 OHMS,1%,1/10W,0603; CLASS: DISCRETE; Inventory Qty: 42882; Manufacturer: VISHAY; Manufacturer PN: CRCW0603200RFKEA; PART_NUMBER: 100-0130; Package Size: 0603; Part Number: VISHAY CRCW0603200RFKEA; Rated Power: 1/10W; Temperature Coefficient: 100ppm; Tolerance: 1%
R28 = RES: RES.,AEC-Q200,127 OHMS,1%,1/10W,0603; CLASS: DISCRETE; FPLIST: CR0603N,CR0603L,CR0603M; Manufacturer: VISHAY; Manufacturer PN: CRCW0603127RFKEA; PART_NUMBER: 100-0054; Package Size: 0603; Part Number: VISHAY CRCW0603127RFKEA; Rated Power: 1/10W; Temperature Coefficient: 100ppm/C; Tolerance: 1%
U2 = 24LC025-I_ST_TSSOP-8: IC, MEMORY,EEPROM,2Kb (256x8),TSSOP-8,400kHz; CLASS: IC; Manufacturer: Microchip; PART_NUMBER: 380-0087; Package Size: TSSOP-8; Package Type: TSSOP-8; Part Number: MICROCHIP 24LC025-I/ST
LB1 = BLANK_LABEL: LABEL SPEC, DEMO BOARD SERIAL NUMBER; Manufacturer: BRADY; Manufacturer PN: THT-96-717-10; PART_NUMBER: 895-0154
MH1-MH4 = MP-PINNED: STANDOFF,NYLON,SNAP-ON,0.25" (6.4mm); CLASS: MECHANICAL PART; Inventory Qty: 191912; Manufacturer: KEYSTONE; Manufacturer PN: 8831; PART_NUMBER: 763-0006
PCB1 = BLANK_PCB_PART: BOM Notes: REV03; CLASS: DISCRETE; Manufacturer: EAGLE TECH. INC.; Manufacturer PN: 600-DC2824A; PART_NUMBER: 600-DC2824A
STNCL1 = BLANK_STENCIL_PART: BOM Notes: REV03; CLASS: DISCRETE; Manufacturer: LINEAR TECH.; Manufacturer PN: 830-DC2824A; PART_NUMBER: 830-DC2824A

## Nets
3V3: E7.1 J1.5(LGKPWR) Q1.2(S) R27.1
GND: C5.2 C41.2 CIN1.2 CIN2.2 CIN3.2 CIN4.2 CIN5.2 CIN6.1 CIN7.1 CIN8.2 CIN9.1 CIN10.1 COUT1.2 COUT2.2 COUT5.2 COUT6.2 COUT7.2 COUT8.2 COUT9.2 COUT10.2 COUT11.2 COUT12.2 E2.1 J1.3(GND) J1.10(GND) J2.1 J3.8(GND) J4.8(GND) J5.2 J5.3 J5.4 J5.5 J6.1 J9.2 J9.3 J9.4 J9.5 JP1.3 JP2.4 JP3.3 JP4.6 JP5.3 JP9.4 Q2.2 R20.2 R28.2 R58.1 R68.1 U1.C7(PGND) U1.F1(PGND) U1.F2(PGND) U1.F3(PGND) U1.F4(PGND) U1.G1(PGND) U1.G2(PGND) U1.G3(PGND) U1.G4(PGND) U2.1(A0) U2.2(A1) U2.3(A2) U2.4(VSS) U2.7(WP)
GND_A: C3.2 C4.2 C7.1 C8.1 C9.2 C11.2 C43.2 E11.1 R2.1 R3.1 R6.1 R11.1 R14.1 R18.2 R21.1 R34.1 R70.2 U1.C3(SGND) U1.C4(SGND)
SVIN: C7.2 R13.1 R22.1 U1.B6(SVIN)
VIN: CIN1.1 CIN2.1 CIN3.1 CIN4.1 CIN5.1 CIN6.2 CIN7.2 CIN8.1 CIN9.2 CIN10.2 J8.1 R13.2 R33.2 U1.H1(PVIN) U1.H2(PVIN) U1.H3(PVIN) U1.H4(PVIN) U1.J1(PVIN) U1.J2(PVIN) U1.J3(PVIN) U1.J4(PVIN)
ALERT: E10.1 J1.6(ALERTB) J3.2(ALERTB) J4.2(ALERTB) Q1.1(G) R8.1 U1.E5(\\~{ALERT})
AUXP: C5.1 J1.1(AUXP) J3.5(AUXP) J4.5(AUXP) R15.1 R16.1 U2.8(VCC)
DAOUT: C6.1 R1.1 U1.A2(DAOUT)
EESCL: J1.11(AUXSCL) R15.2 U2.6(SCL)
EESDA: J1.12(AUXSDA) R16.2 U2.5(SDA)
FB: C1.1 C2.1 R1.2 R17.1 U1.B1(FB)
INTVCC: C11.1 D3.2(A) JP2.1 JP4.2 JP9.1 R8.2 R9.2 R10.2 R12.2 R19.1 R29.2 R69.1 R71.1 U1.B7(INTVCC)
ITH: C1.2 R4.1 U1.A1(ITH)
PGOOD: E3.1 Q2.1 R12.1 U1.C5(PGOOD)
REF: C9.1 C43.1 E13.1 JP6.1 JP7.1 JP8.1 R5.2 U1.B2(REF)
RUN_MSTR: JP1.2 R23.1 R24.1 R33.1 R34.2 U1.A6(RUN_MSTR)
RUN_STBY: JP3.2 R25.1 U1.B5(STBYB)
SCL: E15.1 J1.4(SCL) J3.4(SCL) J4.4(SCL) R10.1 U1.D4(SCL)
SDA: E14.1 J1.2(SDA) J3.3(SDA) J4.3(SDA) R9.1 U1.D5(SDA)
SS: C3.1 E5.1 U1.A3(SS_EXT)
SW: C42.1 L1.1 L2.2 U1.E6(SW) U1.E7(SW) U1.F5(SW) U1.F6(SW) U1.F7(SW) U1.G5(SW) U1.G6(SW) U1.G7(SW) U1.H5(SW) U1.H6(SW) U1.H7(SW) U1.J5(SW) U1.J6(SW) U1.J7(SW)
SYNC: E4.1 JP2.2 JP2.3 R26.1 U1.A7(MODE/SYNC)
VOUT: C41.1 COUT1.1 COUT2.1 COUT5.1 COUT6.1 COUT7.1 COUT8.1 COUT9.1 COUT10.1 COUT11.1 COUT12.1 J5.1 J7.1 L1.2 L2.1 Q15.5(D) Q15.6(VOUT) Q15.7(VOUT) Q15.8(VOUT) R7.2
VSENSE+: R7.1 U1.B3(VCCSEN)
VSENSE-: R20.1 R69.2 U1.B4(VSSSEN)
WP: JP5.2 U1.D3(WP)
N16866343: JP4.1 JP4.3 JP4.5 U1.D2(MARGIN)
N16872501: C4.1 U1.A4(CSLEW)
N16876614: R6.2 U1.D1(ASEL)
N16906456: R3.2 R29.1 U1.C1(RT)
N16909851: E6.1 U1.D6(CLKOUT)
N16910513: R2.2 U1.C6(PGFD)
N16917605: C2.2 R4.2
N16930789: R5.1 R14.2 R19.2 U1.C2(PGLIM)
N17069985: C6.2 R17.2
N17198431: C8.2 E12.1 R22.2
N17265525: J3.6(UNUSED) J4.6(UNUSED) R26.2
N17265543: J3.1(CTRL) J4.1(CTRL) R24.2 R25.2
N17265561: J3.7(UNUSED) J4.7(UNUSED) R23.2
N17437377: JP9.2 JP9.3 R70.1 R71.2 U1.A5(ILIM)
N17484416: R30.2 U1.D7(BOOST)
N17484417: C42.2 D3.1(C) R30.1
N17545537: E1.1 Q15.4(G) R58.2
N17545581: J9.1 Q15.1(S) Q15.2(S) Q15.3(S) R68.2
N17554052: JP6.2 R11.2
N17554200: JP7.2 R18.1
N17554284: JP8.2 R21.2
N17581839: D1.1(CATHODE) Q2.3
N17582410: D2.2(ANODE) Q1.3(D)
N17589624: D2.1(CATHODE) R28.1
N17589625: D1.2(ANODE) R27.2

Not connected (* = marked no-connect by the designer): J1 7(GPIO_1) 8(OUTEN_0) 9(OUTEN_1); JP1 1; JP3 1; JP4 4; JP5 1; MH1 1; MH2 1; MH3 1; MH4 1

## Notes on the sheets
sheet 1
- USED TO MANUFACTURE PCB
- STANDOFFS
sheet 2
- ALL PARTS ON THIS PAGE ARE FOR DEMO BOARD ONLY, NOT NEEDED IN CUSTOMER DESIGN
- TO DC1613A
sheet 3
- REVISION HISTORY
- ECO
- REV
- DESCRIPTION
- DATE
- APPROVED
- -
- 3
- PROTO
- 07/20/21
- L W
- VOUT SEL
- DYNAMIC LOAD CIRCUIT
- DO NOT EXCEED
- 5% DUTY CYCLE!
